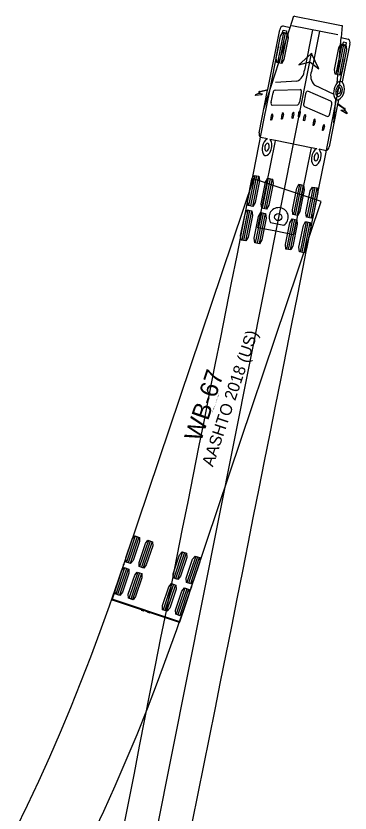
# Model space of a CAD drawing. Extents: x -69 to 14108008, y -6 to 8640172.
# Drawn here: x 14107968.6 to 14108008.4, y 8639947.2 to 8640042.3 of the extents above; entities that cross this region are included whole.
import ezdxf

# ---------------------------------------------------------------- set-up
doc = ezdxf.new("R2010")
doc.units = 0
doc.layers.add('AutoTurn3', color=7, linetype='Continuous')

msp = doc.modelspace()

# ---------------------------------------------------------------- linework, layer by layer
at = {"layer": 'AutoTurn3'}
for p, q in [((14107998.105, 8640031.189), (14108001.234, 8640040.898)), ((14108000.333, 8640040.227), (14108000.403, 8640040.576)), ((14108000.403, 8640040.576), (14108000.808, 8640040.495)), ((14108006.893, 8640039.994), (14108001.438, 8640041.087)), ((14108003.899, 8640040.594), (14108002.938, 8640035.798)), ((14108000.418, 8640040.306), (14107999.703, 8640036.71)), ((14108000.642, 8640040.261), (14107999.928, 8640036.665)), ((14108000.867, 8640040.217), (14108000.153, 8640036.62)), ((14108000.738, 8640040.146), (14108000.333, 8640040.227)), ((14108000.808, 8640040.495), (14108000.738, 8640040.146)), ((14108004.717, 8640040.43), (14108003.756, 8640035.634)), ((14108006.839, 8640034.276), (14108007.293, 8640039.684)), ((14108007.363, 8640038.916), (14108006.649, 8640035.32)), ((14108007.588, 8640038.871), (14108006.873, 8640035.275)), ((14108007.813, 8640038.827), (14108007.098, 8640035.23)), ((14108008.329, 8640038.946), (14108007.416, 8640034.392)), ((14108007.531, 8640039.148), (14108007.461, 8640038.799)), ((14108007.461, 8640038.799), (14108007.865, 8640038.718)), ((14108007.935, 8640039.067), (14108007.531, 8640039.148)), ((14108007.865, 8640038.718), (14108007.935, 8640039.067)), ((14107982.644, 8639931.496), (14108003.758, 8640037.768)), ((14108002.007, 8640034.476), (14107999.464, 8640034.34)), ((14108004.105, 8640034.055), (14108006.412, 8640032.944)), ((14107997.526, 8640033.067), (14107997.501, 8640033.055)), ((14107997.553, 8640033.06), (14107997.526, 8640033.067)), ((14107998.547, 8640033.395), (14107998.567, 8640033.493)), ((14107998.97, 8640031.986), (14107999.192, 8640033.095)), ((14107999.427, 8640033.425), (14108002.433, 8640033.481)), ((14108002.554, 8640033.079), (14108002.332, 8640031.97)), ((14108003.062, 8640032.977), (14108002.84, 8640031.868)), ((14108006.081, 8640032.092), (14108003.329, 8640033.301)), ((14108006.44, 8640029.519), (14108006.674, 8640032.316)), ((14108002.097, 8640031.639), (14107999.092, 8640031.584)), ((14108002.929, 8640031.473), (14108005.682, 8640030.264)), ((14108005.948, 8640030.588), (14108006.171, 8640031.697)), ((14108006.882, 8640031.725), (14108006.901, 8640031.824)), ((14108007.67, 8640031.033), (14108007.698, 8640031.029)), ((14107998.919, 8640029.837), (14107998.989, 8640030.384)), ((14107999.154, 8640030.351), (14107999.007, 8640029.82)), ((14108000.189, 8640029.976), (14108000.262, 8640030.548)), ((14108000.427, 8640030.515), (14108000.277, 8640029.959)), ((14108001.448, 8640030.065), (14108001.518, 8640030.612)), ((14108001.683, 8640030.579), (14108001.536, 8640030.047)), ((14108002.201, 8640030.229), (14108002.271, 8640030.775)), ((14108002.29, 8640030.211), (14108002.201, 8640030.229)), ((14108002.436, 8640030.742), (14108002.29, 8640030.211)), ((14108002.834, 8640029.787), (14108002.903, 8640030.334)), ((14108003.068, 8640030.301), (14108002.922, 8640029.77)), ((14108007.698, 8640031.029), (14108007.716, 8640031.008)), ((14107999.007, 8640029.82), (14107998.919, 8640029.837)), ((14108000.277, 8640029.959), (14108000.189, 8640029.976)), ((14108001.536, 8640030.047), (14108001.448, 8640030.065)), ((14108002.922, 8640029.77), (14108002.834, 8640029.787)), ((14108003.962, 8640029.221), (14108004.031, 8640029.767)), ((14108004.05, 8640029.203), (14108003.962, 8640029.221)), ((14108004.196, 8640029.734), (14108004.05, 8640029.203)), ((14108005.08, 8640028.603), (14108005.149, 8640029.15)), ((14108005.168, 8640028.586), (14108005.08, 8640028.603)), ((14108005.314, 8640029.117), (14108005.168, 8640028.586)), ((14107998.524, 8640027.598), (14107997.696, 8640027.764)), ((14108003.72, 8640026.557), (14107999.474, 8640027.408)), ((14108005.498, 8640026.201), (14108004.669, 8640026.367)), ((14107997.002, 8640023.246), (14107996.282, 8640019.65)), ((14107997.227, 8640023.201), (14107996.507, 8640019.605)), ((14107997.452, 8640023.156), (14107996.732, 8640019.56)), ((14107998.62, 8640022.921), (14107997.9, 8640019.326)), ((14107998.845, 8640022.876), (14107998.125, 8640019.281)), ((14107999.07, 8640022.831), (14107998.349, 8640019.236)), ((14108002.33, 8640022.178), (14108001.61, 8640018.583)), ((14108002.555, 8640022.133), (14108001.834, 8640018.538)), ((14108002.779, 8640022.088), (14108002.059, 8640018.493)), ((14108003.948, 8640021.854), (14108003.227, 8640018.259)), ((14108004.172, 8640021.809), (14108003.452, 8640018.214)), ((14108004.397, 8640021.764), (14108003.677, 8640018.169)), ((14107996.177, 8640019.127), (14107995.457, 8640015.532)), ((14107996.402, 8640019.082), (14107995.682, 8640015.487)), ((14107996.627, 8640019.037), (14107995.906, 8640015.442)), ((14107997.795, 8640018.803), (14107997.075, 8640015.208)), ((14107998.02, 8640018.758), (14107997.3, 8640015.163)), ((14107998.245, 8640018.713), (14107997.524, 8640015.118)), ((14108001.505, 8640018.06), (14108000.785, 8640014.465)), ((14108001.73, 8640018.015), (14108001.009, 8640014.42)), ((14108001.954, 8640017.97), (14108001.234, 8640014.375)), ((14108003.123, 8640017.736), (14108002.402, 8640014.141)), ((14107998.904, 8640017.631), (14108000.489, 8640017.313)), ((14108003.347, 8640017.691), (14108002.627, 8640014.096)), ((14108003.572, 8640017.646), (14108002.852, 8640014.051)), ((14107982.786, 8639980.258), (14107981.735, 8639977.13)), ((14107983.004, 8639980.185), (14107981.952, 8639977.057)), ((14107983.221, 8639980.112), (14107982.17, 8639976.984)), ((14107984.35, 8639979.733), (14107983.299, 8639976.605)), ((14107984.568, 8639979.66), (14107983.517, 8639976.532)), ((14107984.785, 8639979.587), (14107983.734, 8639976.459)), ((14107988.411, 8639978.368), (14107987.36, 8639975.24)), ((14107988.628, 8639978.295), (14107987.577, 8639975.167)), ((14107988.845, 8639978.222), (14107987.794, 8639975.094)), ((14107989.975, 8639977.843), (14107988.924, 8639974.715)), ((14107990.192, 8639977.77), (14107989.141, 8639974.642)), ((14107990.409, 8639977.697), (14107989.358, 8639974.569)), ((14107981.512, 8639976.467), (14107980.461, 8639973.338)), ((14107981.73, 8639976.394), (14107980.678, 8639973.265)), ((14107981.947, 8639976.321), (14107980.896, 8639973.192)), ((14107983.076, 8639975.941), (14107982.025, 8639972.813)), ((14107983.294, 8639975.868), (14107982.243, 8639972.74)), ((14107983.511, 8639975.795), (14107982.46, 8639972.667)), ((14107987.137, 8639974.577), (14107986.086, 8639971.449)), ((14107987.354, 8639974.504), (14107986.303, 8639971.376)), ((14107987.571, 8639974.431), (14107986.52, 8639971.303)), ((14107988.701, 8639974.051), (14107987.65, 8639970.923)), ((14107988.918, 8639973.978), (14107987.867, 8639970.85)), ((14107989.135, 8639973.905), (14107988.084, 8639970.777)), ((14107988.076, 8639970.032), (14107980.018, 8639972.739)), ((14107983.773, 8639971.404), (14107983.521, 8639971.488)), ((14107983.779, 8639971.401), (14107984.273, 8639971.235)), ((14107984.024, 8639971.319), (14107984.047, 8639971.386)), ((14107984.528, 8639971.15), (14107984.276, 8639971.234))]:
    msp.add_line(p, q, dxfattribs=at)
for points in [[(14108000.385, 8640041.068), (14108001.225, 8640040.9), (14108001.234, 8640040.9), (14108001.674, 8640042.265), (14108001.736, 8640042.253), (14108004.544, 8640041.69), (14108007.351, 8640041.128), (14108007.413, 8640041.115), (14108007.293, 8640039.686), (14108007.301, 8640039.683), (14108008.142, 8640039.514)], [(14107997.588, 8640033.263), (14107998.557, 8640033.491), (14107998.569, 8640033.501), (14107999.994, 8640040.616)], [(14107981.439, 8639945.625), (14107982.052, 8639948.806), (14107982.673, 8639951.999), (14107983.3, 8639955.204), (14107983.932, 8639958.418), (14107984.567, 8639961.64), (14107985.205, 8639964.87), (14107985.846, 8639968.105), (14107986.488, 8639971.346), (14107987.131, 8639974.592), (14107987.776, 8639977.841), (14107988.421, 8639981.093), (14107989.068, 8639984.348), (14107989.714, 8639987.605), (14107990.362, 8639990.865), (14107991.009, 8639994.126), (14107991.657, 8639997.388), (14107992.306, 8640000.651), (14107992.954, 8640003.916), (14107993.603, 8640007.181), (14107994.252, 8640010.447), (14107994.901, 8640013.714), (14107995.55, 8640016.981), (14107996.199, 8640020.249), (14107996.848, 8640023.517), (14107997.498, 8640026.785), (14107998.147, 8640030.053), (14107998.796, 8640033.322), (14107999.446, 8640036.591), (14107999.835, 8640038.552)], [(14108003.758, 8640037.768), (14108002.254, 8640036.449), (14108003.563, 8640036.787), (14108004.643, 8640035.975), (14108003.758, 8640037.768)], [(14107989.601, 8639946.223), (14107990.28, 8639949.572), (14107990.953, 8639952.909), (14107991.621, 8639956.236), (14107992.285, 8639959.554), (14107992.946, 8639962.865), (14107993.605, 8639966.169), (14107994.262, 8639969.469), (14107994.918, 8639972.763), (14107995.573, 8639976.054), (14107996.227, 8639979.342), (14107996.88, 8639982.627), (14107997.532, 8639985.909), (14107998.184, 8639989.19), (14107998.836, 8639992.469), (14107999.487, 8639995.746), (14108000.138, 8639999.023), (14108000.789, 8640002.298), (14108001.44, 8640005.573), (14108002.09, 8640008.846), (14108002.74, 8640012.12), (14108003.391, 8640015.392), (14108004.041, 8640018.665), (14108004.691, 8640021.936), (14108005.341, 8640025.208), (14108005.991, 8640028.479), (14108006.64, 8640031.75), (14108007.29, 8640035.021), (14108007.68, 8640036.984)], [(14107997.53, 8640028.32), (14107998.547, 8640033.395), (14107997.589, 8640033.174), (14107997.589, 8640033.174), (14107997.57, 8640033.14), (14107997.57, 8640033.14), (14107997.57, 8640033.139), (14107997.553, 8640033.061), (14107997.554, 8640033.06), (14107997.892, 8640032.976), (14107997.872, 8640032.875), (14107997.116, 8640032.764), (14107997.115, 8640032.765), (14107997.138, 8640032.881), (14107997.141, 8640032.883), (14107997.499, 8640033.054), (14107997.501, 8640033.056), (14107997.518, 8640033.14)], [(14108006.987, 8640032.249), (14108006.903, 8640031.832), (14108006.909, 8640031.818), (14108007.716, 8640031.234)], [(14108007.733, 8640031.094), (14108007.717, 8640031.009), (14108007.718, 8640031.006), (14108007.982, 8640030.711), (14108007.984, 8640030.708), (14108007.961, 8640030.592), (14108007.959, 8640030.592), (14108007.304, 8640030.985), (14108007.324, 8640031.086), (14108007.669, 8640031.033), (14108007.67, 8640031.034), (14108007.685, 8640031.112), (14108007.685, 8640031.113), (14108007.685, 8640031.114), (14108007.681, 8640031.152), (14108007.68, 8640031.152), (14108006.882, 8640031.725), (14108005.865, 8640026.65)], [(14108004.393, 8640026.422), (14108003.721, 8640026.557), (14108003.673, 8640026.324), (14108001.638, 8640016.164), (14107999.515, 8640016.589), (14107997.392, 8640017.014), (14107999.427, 8640027.174), (14107999.473, 8640027.408), (14107998.801, 8640027.543)], [(14107988.032, 8639969.972), (14107988.052, 8639969.966), (14107988.075, 8639970.032), (14107989.881, 8639975.404), (14108004.911, 8640020.138), (14108000.883, 8640021.492), (14107996.854, 8640022.845), (14107981.823, 8639978.112), (14107980.019, 8639972.739), (14107979.996, 8639972.672), (14107980.017, 8639972.665)], [(14107968.576, 8639945.323), (14107969.967, 8639948.148), (14107971.316, 8639951.014), (14107972.624, 8639953.917), (14107973.893, 8639956.853), (14107975.124, 8639959.82), (14107976.32, 8639962.813), (14107977.481, 8639965.832), (14107978.61, 8639968.873), (14107979.709, 8639971.935), (14107980.778, 8639975.015), (14107981.407, 8639976.871)], [(14107977.623, 8639944.455), (14107979.034, 8639947.453), (14107980.398, 8639950.48), (14107981.718, 8639953.533), (14107982.995, 8639956.61), (14107984.232, 8639959.707), (14107985.431, 8639962.823), (14107986.594, 8639965.956), (14107987.723, 8639969.103), (14107988.82, 8639972.262), (14107989.464, 8639974.164)], [(14107980.04, 8639972.658), (14107980.041, 8639972.657), (14107983.487, 8639971.5), (14107983.521, 8639971.488), (14107983.499, 8639971.422), (14107983.5, 8639971.421), (14107983.753, 8639971.336)], [(14107984.251, 8639971.168), (14107984.504, 8639971.083), (14107984.506, 8639971.083), (14107984.528, 8639971.15), (14107984.562, 8639971.138), (14107988.008, 8639969.98), (14107988.009, 8639969.98)]]:
    msp.add_lwpolyline(points, dxfattribs=at)
for points in [[(14108000.362, 8640040.317), (14108000.923, 8640040.206), (14108000.992, 8640039.669), (14108000.477, 8640037.079), (14108000.208, 8640036.609), (14107999.647, 8640036.721), (14107999.578, 8640037.258), (14108000.093, 8640039.847)], [(14108007.307, 8640038.927), (14108007.868, 8640038.816), (14108007.937, 8640038.278), (14108007.423, 8640035.689), (14108007.154, 8640035.219), (14108006.593, 8640035.331), (14108006.524, 8640035.868), (14108007.038, 8640038.457)], [(14108003.758, 8640037.768), (14108002.254, 8640036.449), (14108003.563, 8640036.787), (14108004.643, 8640035.975)], [(14107996.947, 8640023.257), (14107997.508, 8640023.144), (14107997.576, 8640022.607), (14107997.057, 8640020.019), (14107996.787, 8640019.549), (14107996.226, 8640019.661), (14107996.158, 8640020.199), (14107996.677, 8640022.787)], [(14107998.565, 8640022.933), (14107999.125, 8640022.82), (14107999.194, 8640022.283), (14107998.675, 8640019.694), (14107998.405, 8640019.225), (14107997.844, 8640019.337), (14107997.776, 8640019.875), (14107998.295, 8640022.463)], [(14108002.274, 8640022.189), (14108002.835, 8640022.077), (14108002.903, 8640021.54), (14108002.385, 8640018.951), (14108002.115, 8640018.482), (14108001.554, 8640018.594), (14108001.486, 8640019.131), (14108002.004, 8640021.72)], [(14108003.892, 8640021.865), (14108004.453, 8640021.753), (14108004.521, 8640021.216), (14108004.002, 8640018.627), (14108003.733, 8640018.158), (14108003.172, 8640018.27), (14108003.104, 8640018.807), (14108003.622, 8640021.396)], [(14107996.122, 8640019.139), (14107996.683, 8640019.026), (14107996.751, 8640018.489), (14107996.232, 8640015.9), (14107995.962, 8640015.431), (14107995.401, 8640015.543), (14107995.333, 8640016.081), (14107995.852, 8640018.669)], [(14107997.74, 8640018.814), (14107998.3, 8640018.702), (14107998.369, 8640018.165), (14107997.85, 8640015.576), (14107997.58, 8640015.107), (14107997.019, 8640015.219), (14107996.951, 8640015.756), (14107997.47, 8640018.345)], [(14108001.449, 8640018.071), (14108002.01, 8640017.959), (14108002.078, 8640017.422), (14108001.56, 8640014.833), (14108001.29, 8640014.364), (14108000.729, 8640014.476), (14108000.661, 8640015.013), (14108001.179, 8640017.602)], [(14108003.067, 8640017.747), (14108003.628, 8640017.635), (14108003.696, 8640017.097), (14108003.177, 8640014.509), (14108002.908, 8640014.039), (14108002.347, 8640014.152), (14108002.279, 8640014.689), (14108002.797, 8640017.278)], [(14107982.732, 8639980.276), (14107983.275, 8639980.094), (14107983.291, 8639979.601), (14107982.534, 8639977.349), (14107982.224, 8639976.966), (14107981.681, 8639977.148), (14107981.665, 8639977.641), (14107982.422, 8639979.893)], [(14107984.296, 8639979.751), (14107984.839, 8639979.569), (14107984.855, 8639979.076), (14107984.098, 8639976.824), (14107983.788, 8639976.44), (14107983.245, 8639976.623), (14107983.229, 8639977.115), (14107983.986, 8639979.368)], [(14107988.357, 8639978.387), (14107988.899, 8639978.204), (14107988.915, 8639977.712), (14107988.158, 8639975.459), (14107987.848, 8639975.076), (14107987.306, 8639975.258), (14107987.289, 8639975.751), (14107988.046, 8639978.003)], [(14107989.921, 8639977.861), (14107990.463, 8639977.679), (14107990.479, 8639977.186), (14107989.722, 8639974.934), (14107989.412, 8639974.551), (14107988.87, 8639974.733), (14107988.854, 8639975.226), (14107989.61, 8639977.478)], [(14107981.458, 8639976.485), (14107982.001, 8639976.302), (14107982.017, 8639975.81), (14107981.26, 8639973.557), (14107980.95, 8639973.174), (14107980.407, 8639973.357), (14107980.391, 8639973.849), (14107981.148, 8639976.102)], [(14107983.022, 8639975.959), (14107983.565, 8639975.777), (14107983.581, 8639975.284), (14107982.824, 8639973.032), (14107982.514, 8639972.649), (14107981.971, 8639972.831), (14107981.955, 8639973.324), (14107982.712, 8639975.576)], [(14107987.083, 8639974.595), (14107987.625, 8639974.413), (14107987.641, 8639973.92), (14107986.884, 8639971.668), (14107986.574, 8639971.285), (14107986.032, 8639971.467), (14107986.015, 8639971.96), (14107986.772, 8639974.212)], [(14107988.647, 8639974.069), (14107989.189, 8639973.887), (14107989.205, 8639973.394), (14107988.448, 8639971.142), (14107988.138, 8639970.759), (14107987.596, 8639970.941), (14107987.58, 8639971.434), (14107988.336, 8639973.686)]]:
    msp.add_lwpolyline(points, close=True, dxfattribs=at)
for centre, radius in [((14107999.835, 8640038.552), 0.0417), ((14108003.758, 8640037.768), 0.0417), ((14108007.68, 8640036.984), 0.0417), ((14107999.803, 8640018.28), 0.424), ((14107981.407, 8639976.871), 0.0417), ((14107989.464, 8639974.164), 0.0417), ((14107980.017, 8639972.629), 0.0266), ((14107988.01, 8639969.944), 0.0266)]:
    msp.add_circle(centre, radius, dxfattribs=at)
for centre, radius, start, end in [((14108000.479, 8640040.592), 0.486, 101.13373, 177.08484), ((14108007.871, 8640039.111), 0.486, 340.25669, 56.2078), ((14108001.423, 8640035.875), 1.517, 292.6633, 357.09072), ((14108005.183, 8640035.122), 1.517, 160.25081, 224.67822), ((14108008.117, 8640033.149), 1.704, 138.59145, 174.49952), ((14108007.159, 8640033.653), 0.366, 86.7231, 159.20409), ((14108007.18, 8640034.022), 0.425, 56.7337, 143.27006), ((14108006.15, 8640033.533), 1.53, 303.1635, 34.17255), ((14108006.818, 8640033.497), 0.634, 339.25463, 55.25634), ((14107997.615, 8640033.187), 0.108, 159.51194, 205.69443), ((14107997.566, 8640033.215), 0.0522, 64.93355, 169.78817), ((14107999.578, 8640033.069), 0.387, 113.00361, 176.23558), ((14108002.293, 8640033.219), 0.296, 331.65433, 61.95201), ((14108003.357, 8640033.006), 0.296, 95.38952, 185.6872), ((14108007.53, 8640033.064), 1.136, 167.37531, 221.17787), ((14108007.845, 8640033.185), 1.189, 149.80197, 185.69128), ((14108007.101, 8640033.07), 0.44, 180.46501, 244.27786), ((14108007.101, 8640033.23), 0.263, 167.60568, 241.5076), ((14108007.42, 8640033.27), 0.575, 141.74588, 178.31621), ((14108007.097, 8640033.536), 0.158, 83.64199, 145.15474), ((14108006.986, 8640033.169), 0.17, 266.33983, 320.40416), ((14108007.022, 8640033.49), 0.223, 355.90567, 65.50816), ((14108006.657, 8640033.428), 0.589, 321.42629, 4.409), ((14108006.398, 8640033.453), 1.03, 321.49442, 349.88093), ((14107999.277, 8640031.86), 0.332, 157.59217, 236.01417), ((14108005.805, 8640031.822), 0.387, 341.10595, 44.33792), ((14108006.893, 8640032.586), 0.347, 230.99798, 285.80856), ((14108006.941, 8640032.989), 0.317, 264.52096, 326.11336), ((14108001.946, 8640031.995), 0.387, 293.00606, 356.23313), ((14108003.206, 8640031.743), 0.387, 161.1084, 224.33546), ((14108007.718, 8640031.182), 0.0522, 347.55336, 92.40798), ((14108007.661, 8640031.174), 0.108, 311.6471, 357.82959), ((14107999.144, 8640030.409), 0.157, 102.21675, 189.32641), ((14107998.986, 8640030.427), 0.184, 335.62394, 47.51596), ((14108000.413, 8640030.548), 0.157, 102.21675, 189.32641), ((14108000.256, 8640030.566), 0.184, 335.62394, 47.51596), ((14108001.673, 8640030.637), 0.157, 102.21675, 189.32641), ((14108001.515, 8640030.655), 0.184, 335.62394, 47.51596), ((14108002.426, 8640030.801), 0.157, 102.21675, 189.32641), ((14108002.303, 8640030.825), 0.157, 328.01512, 55.12478), ((14108003.087, 8640030.34), 0.184, 109.82557, 181.71759), ((14108002.935, 8640030.384), 0.157, 328.01512, 55.12478), ((14108005.616, 8640030.589), 0.332, 281.32736, 359.74936), ((14108004.215, 8640029.773), 0.184, 109.82557, 181.71759), ((14108004.063, 8640029.817), 0.157, 328.01512, 55.12478), ((14108005.333, 8640029.155), 0.184, 109.82557, 181.71759), ((14108005.181, 8640029.2), 0.157, 328.01512, 55.12478), ((14107998.137, 8640028.198), 0.619, 168.66874, 224.51045), ((14107999.063, 8640026.598), 1.136, 118.3007, 173.09199), ((14107998.304, 8640027.01), 0.729, 4.47925, 46.99325), ((14107999.313, 8640026.406), 1.416, 166.59892, 203.66677), ((14107998.867, 8640026.517), 0.664, 163.57459, 201.79631), ((14107998.745, 8640026.622), 0.522, 123.67613, 170.84025), ((14107998.533, 8640026.907), 0.169, 17.10509, 117.22381), ((14107998.319, 8640026.494), 0.362, 292.96733, 342.00831), ((14107997.862, 8640026.602), 1.136, 304.43473, 345.95547), ((14107998.007, 8640026.705), 0.732, 333.84459, 20.07902), ((14107997.314, 8640026.847), 1.73, 342.4974, 7.29591), ((14108004.646, 8640025.739), 0.729, 110.34828, 152.86228), ((14108003.787, 8640025.651), 1.136, 344.24954, 39.04083), ((14108005.258, 8640026.772), 0.619, 292.83108, 348.67279), ((14107998.336, 8640025.968), 0.346, 202.06346, 299.07652), ((14107998.413, 8640026.326), 0.172, 198.97237, 286.12296), ((14108004.897, 8640025.193), 1.136, 171.38606, 212.9068), ((14108005.497, 8640025.207), 1.73, 150.04562, 174.84413), ((14108004.803, 8640025.344), 0.732, 137.2625, 183.49694), ((14108004.395, 8640025.732), 0.169, 40.11772, 140.23644), ((14108003.937, 8640025.501), 0.664, 315.54522, 353.76693), ((14108003.483, 8640025.571), 1.416, 313.67476, 350.74261), ((14108004.09, 8640025.551), 0.522, 346.50128, 33.6654), ((14108004.215, 8640024.79), 0.346, 218.26501, 315.27807), ((14108004.434, 8640025.269), 0.362, 175.33322, 224.3742), ((14108004.283, 8640025.15), 0.172, 231.21857, 318.36916), ((14107999.855, 8640018.265), 1.143, 303.67076, 213.67076), ((14107980.017, 8639972.629), 0.0363, 90.50495, 51.6663), ((14107983.763, 8639971.37), 0.0353, 74.76368, 253.11333), ((14107983.764, 8639971.369), 0.0352, 251.45277, 70.45318), ((14107984.262, 8639971.202), 0.0352, 72.40182, 251.40223), ((14107984.263, 8639971.202), 0.0354, 255.71904, 67.9045), ((14107987.388, 8639968.056), 2.022, 71.4275, 72.11126)]:
    msp.add_arc(centre, radius, start, end, dxfattribs=at)
for centre, major_axis, start_param, end_param in [((14107997.553, 8640033.202), (0.0154, 0.0767), 2.615166, 3.884468), ((14107997.553, 8640033.202), (-0.0154, -0.0767), 1.301202, 2.571945), ((14108007.725, 8640031.164), (0.0154, 0.0767), 0.569648, 1.840391), ((14108007.725, 8640031.164), (0.0154, 0.0767), 2.398717, 3.668019)]:
    msp.add_ellipse(centre, major_axis=major_axis, ratio=0.544872, start_param=start_param, end_param=end_param, dxfattribs=at)

# ---------------------------------------------------------------- texts
for s, height, p in [('AASHTO 2018 (US)', 1.41667, (14107992.022, 8639988.427)), ('WB-67', 2.125, (14107990.589, 8639991.39)), ('(c) 2023 Transoft Solutions, Inc. All rights reserved.', 0.085, (14107991.928, 8639994.709))]:
    msp.add_text(s, height=height, rotation=71.4275, dxfattribs=at).set_placement(p)

doc.saveas('drawing.dxf')
